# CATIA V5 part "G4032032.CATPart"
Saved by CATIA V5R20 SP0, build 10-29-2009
Part number: G4032032
Revision: 4
Definition: design
Nomenclature: G4032032
Source: made
Description: NOT SPECIFIED
Bounding box of the stored display mesh (mm): x -16 to 16, y -16 to 16, z -16 to 16
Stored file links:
  C:\Users\Raffaele\Desktop\3D X SITO CF\BOLEX\27-BUSH REF 403\G4032032.CATPart
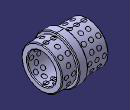
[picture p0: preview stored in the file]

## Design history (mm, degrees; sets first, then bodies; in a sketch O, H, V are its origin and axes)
Body1 "MANIFOLD_SOLID_BREP #9169" (main body)
  Solid1: solid without history
Body2 "MANIFOLD_SOLID_BREP #9312"
  Solid2: solid without history
Body3 "MANIFOLD_SOLID_BREP #9455"
  Solid3: solid without history
Body4 "MANIFOLD_SOLID_BREP #9598"
  Solid4: solid without history
Body5 "MANIFOLD_SOLID_BREP #9741"
  Solid5: solid without history
Body6 "MANIFOLD_SOLID_BREP #9886"
  Solid6: solid without history
Body7 "MANIFOLD_SOLID_BREP #10031"
  Solid7: solid without history
Body8 "MANIFOLD_SOLID_BREP #10176"
  Solid8: solid without history
Body9 "MANIFOLD_SOLID_BREP #10321"
  Solid9: solid without history
Body10 "MANIFOLD_SOLID_BREP #10466"
  Solid10: solid without history
Body11 "MANIFOLD_SOLID_BREP #10611"
  Solid11: solid without history
Body12 "MANIFOLD_SOLID_BREP #10756"
  Solid12: solid without history
Body13 "MANIFOLD_SOLID_BREP #10901"
  Solid13: solid without history
Body14 "MANIFOLD_SOLID_BREP #11046"
  Solid14: solid without history
Body15 "MANIFOLD_SOLID_BREP #11191"
  Solid15: solid without history
Body16 "MANIFOLD_SOLID_BREP #11336"
  Solid16: solid without history
Body17 "MANIFOLD_SOLID_BREP #11481"
  Solid17: solid without history
Body18 "MANIFOLD_SOLID_BREP #11626"
  Solid18: solid without history
Body19 "MANIFOLD_SOLID_BREP #11771"
  Solid19: solid without history
Body20 "MANIFOLD_SOLID_BREP #11916"
  Solid20: solid without history
Body21 "MANIFOLD_SOLID_BREP #12061"
  Solid21: solid without history
Body22 "MANIFOLD_SOLID_BREP #12208"
  Solid22: solid without history
Body23 "MANIFOLD_SOLID_BREP #12353"
  Solid23: solid without history
Body24 "MANIFOLD_SOLID_BREP #12498"
  Solid24: solid without history
Body25 "MANIFOLD_SOLID_BREP #12645"
  Solid25: solid without history
Body26 "MANIFOLD_SOLID_BREP #12790"
  Solid26: solid without history
Body27 "MANIFOLD_SOLID_BREP #12935"
  Solid27: solid without history
Body28 "MANIFOLD_SOLID_BREP #13080"
  Solid28: solid without history
Body29 "MANIFOLD_SOLID_BREP #13225"
  Solid29: solid without history
Body30 "MANIFOLD_SOLID_BREP #13370"
  Solid30: solid without history
Body31 "MANIFOLD_SOLID_BREP #13515"
  Solid31: solid without history
Body32 "MANIFOLD_SOLID_BREP #13658"
  Solid32: solid without history
Body33 "MANIFOLD_SOLID_BREP #13801"
  Solid33: solid without history
Body34 "MANIFOLD_SOLID_BREP #13946"
  Solid34: solid without history
Body35 "MANIFOLD_SOLID_BREP #14091"
  Solid35: solid without history
Body36 "MANIFOLD_SOLID_BREP #14236"
  Solid36: solid without history
Body37 "MANIFOLD_SOLID_BREP #14381"
  Solid37: solid without history
Body38 "MANIFOLD_SOLID_BREP #14526"
  Solid38: solid without history
Body39 "MANIFOLD_SOLID_BREP #14671"
  Solid39: solid without history
Body40 "MANIFOLD_SOLID_BREP #14816"
  Solid40: solid without history
Body41 "MANIFOLD_SOLID_BREP #14961"
  Solid41: solid without history
Body42 "MANIFOLD_SOLID_BREP #15106"
  Solid42: solid without history
Body43 "MANIFOLD_SOLID_BREP #15251"
  Solid43: solid without history
Body44 "MANIFOLD_SOLID_BREP #15396"
  Solid44: solid without history
Body45 "MANIFOLD_SOLID_BREP #15541"
  Solid45: solid without history
Body46 "MANIFOLD_SOLID_BREP #15686"
  Solid46: solid without history
Body47 "MANIFOLD_SOLID_BREP #15831"
  Solid47: solid without history
Body48 "MANIFOLD_SOLID_BREP #15976"
  Solid48: solid without history
Body49 "MANIFOLD_SOLID_BREP #16121"
  Solid49: solid without history
Body50 "MANIFOLD_SOLID_BREP #16268"
  Solid50: solid without history
Body51 "MANIFOLD_SOLID_BREP #16413"
  Solid51: solid without history
Body52 "MANIFOLD_SOLID_BREP #16558"
  Solid52: solid without history
Body53 "MANIFOLD_SOLID_BREP #16705"
  Solid53: solid without history
Body54 "MANIFOLD_SOLID_BREP #16848"
  Solid54: solid without history
Body55 "MANIFOLD_SOLID_BREP #16991"
  Solid55: solid without history
Body56 "MANIFOLD_SOLID_BREP #17134"
  Solid56: solid without history
Body57 "MANIFOLD_SOLID_BREP #17277"
  Solid57: solid without history
Body58 "MANIFOLD_SOLID_BREP #17422"
  Solid58: solid without history
Body59 "MANIFOLD_SOLID_BREP #17567"
  Solid59: solid without history
Body60 "MANIFOLD_SOLID_BREP #17712"
  Solid60: solid without history
Body61 "MANIFOLD_SOLID_BREP #17857"
  Solid61: solid without history
Body62 "MANIFOLD_SOLID_BREP #18004"
  Solid62: solid without history
Body63 "MANIFOLD_SOLID_BREP #18149"
  Solid63: solid without history
Body64 "MANIFOLD_SOLID_BREP #18294"
  Solid64: solid without history
Body65 "MANIFOLD_SOLID_BREP #18441"
  Solid65: solid without history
